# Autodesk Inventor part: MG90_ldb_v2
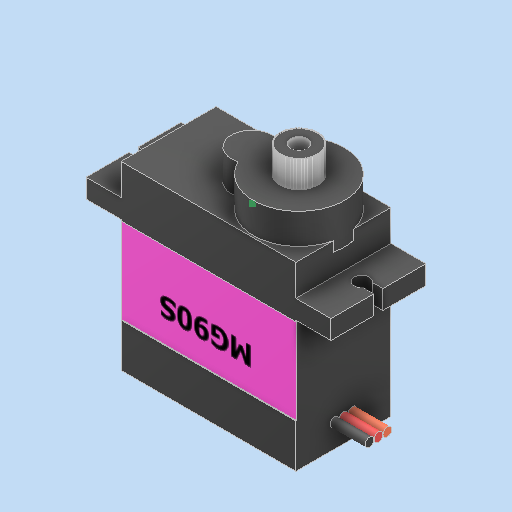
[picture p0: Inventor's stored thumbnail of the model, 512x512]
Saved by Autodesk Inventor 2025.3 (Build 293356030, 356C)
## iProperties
Created: 2019-07
Part Number: MG90_ldb_v2
Material: Steel
Document SubType Name: Modeling
Designer: Ryzen5700u
Density: 7.85 g/cm^3
Appearance: Default
Author: Ryzen5700u
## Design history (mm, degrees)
node "Geometria corretta1"
  node "Schizzo8-Invisible"
node "Solido1"
sketch "Schizzo2-Invisible"
sketch "Schizzo9-Invisible"
node "Schizzo11-Invisible"
node "Schizzo12-Invisible"
node "Schizzo6-Invisible"
sketch "Schizzo10-Invisible"
node "Schizzo7-Invisible"
node "Schizzo13-Invisible"
sketch "Schizzo1"
  geometry: L1 (23, -4.915)-(23, 0) reference; L2 (23, 0)-(0, 0) reference; L3 (0, 0)-(0, -12.5) reference; L4 (0, -12.5)-(23, -12.5) reference; L5 (23, -12.5)-(23, -7.585) reference; A1 r 6 centre (17.15, -6.25) between (23, -4.915) and (11.734, -3.666) reference; A2 r 6 centre (17.15, -6.25) between (11.734, -8.834) and (23, -7.585) reference; A3 r 2.7 centre (10.95, -6.25) between (11.734, -3.666) and (11.734, -8.834) reference; 1 further point
extrude "Estrusione1" join sketch "Schizzo1" distance "d0" = 1.3; taper "d1" = 0 deg
sketch "Schizzo2"
  geometry: L1 (4.6, 0)-(4.6, -12.5) reference; L2 (4.6, 0)-(0, 0) reference; L3 (0, 0)-(0, -5.65) reference; L4 (1.4, -5.65)-(0, -5.65) reference; L5 (1.4, -6.85)-(0, -6.85) reference; L6 (0, -6.85)-(0, -12.5) reference; L7 (4.6, -12.5)-(0, -12.5) reference; L8 (27.6, -12.5)-(27.6, 0) reference; L9 (27.6, -12.5)-(32.2, -12.5) reference; L10 (32.2, -12.5)-(32.2, -6.85) reference; L11 (30.8, -6.85)-(32.2, -6.85) reference; L12 (30.8, -5.65)-(32.2, -5.65) reference; L13 (32.2, -5.65)-(32.2, 0) reference; L14 (27.6, 0)-(32.2, 0) reference; A1 r 1 centre (2.2, -6.25) between (1.4, -6.85) and (1.4, -5.65) reference; A2 r 1 centre (30, -6.25) between (30.8, -5.65) and (30.8, -6.85) reference; 1 further point
extrude "Estrusione2" cut sketch "Schizzo2" distance "d5" = 1.8; taper "d6" = 0 deg
sketch "Schizzo3"
  geometry: L1 (4.6, 0)-(4.6, -12.5) reference; L2 (4.6, 0)-(0, 0) reference; L3 (0, 0)-(0, -5.65) reference; L4 (0, -5.65)-(1.4, -5.65) reference; L5 (1.4, -6.85)-(0, -6.85) reference; L6 (0, -6.85)-(0, -12.5) reference; L7 (4.6, -12.5)-(0, -12.5) reference; L8 (27.6, -12.5)-(27.6, 0) reference; L9 (27.6, -12.5)-(32.2, -12.5) reference; L10 (32.2, -12.5)-(32.2, -6.85) reference; L11 (32.2, -6.85)-(30.8, -6.85) reference; L12 (30.8, -5.65)-(32.2, -5.65) reference; L13 (32.2, -5.65)-(32.2, 0) reference; L14 (27.6, 0)-(32.2, 0) reference; A1 r 1 centre (2.2, -6.25) between (1.4, -6.85) and (1.4, -5.65) reference; A2 r 1 centre (30, -6.25) between (30.8, -5.65) and (30.8, -6.85) reference; 1 further point
extrude "Estrusione3" join sketch "Schizzo3" distance "d7" = 1.5; taper "d8" = 0 deg
sketch "Schizzo4"
  geometry: L1 (-0.548, -2.337)-(-0.45, -2.358) reference; L2 (-0.569, -2.434)-(-0.548, -2.337) reference; L3 (-0.694, -2.298)-(-0.725, -2.393) reference; L4 (-0.789, -2.267)-(-0.694, -2.298) reference; L5 (-0.82, -2.362)-(-0.789, -2.267) reference; L6 (-0.93, -2.213)-(-0.971, -2.304) reference; L7 (-1.022, -2.172)-(-0.93, -2.213) reference; L8 (-1.062, -2.263)-(-1.022, -2.172) reference; L9 (-1.157, -2.103)-(-1.206, -2.19) reference; L10 (-1.243, -2.053)-(-1.157, -2.103) reference; L11 (-1.293, -2.14)-(-1.243, -2.053) reference; L12 (-1.37, -1.971)-(-1.429, -2.052) reference; L13 (-1.451, -1.912)-(-1.37, -1.971) reference; L14 (-1.51, -1.993)-(-1.451, -1.912) reference; L15 (-1.569, -1.817)-(-1.635, -1.891) reference; L16 (-1.643, -1.75)-(-1.569, -1.817) reference; L17 (-1.71, -1.824)-(-1.643, -1.75) reference; L18 (-1.75, -1.643)-(-1.824, -1.71) reference; L19 (-1.817, -1.569)-(-1.75, -1.643) reference; L20 (-1.891, -1.635)-(-1.817, -1.569) reference; L21 (-1.912, -1.451)-(-1.993, -1.51) reference; L22 (-1.971, -1.37)-(-1.912, -1.451) reference; L23 (-2.052, -1.429)-(-1.971, -1.37) reference; L24 (-2.053, -1.243)-(-2.14, -1.293) reference; L25 (-2.103, -1.157)-(-2.053, -1.243) reference; L26 (-2.19, -1.206)-(-2.103, -1.157) reference; L27 (-2.172, -1.022)-(-2.263, -1.062) reference; L28 (-2.213, -0.93)-(-2.172, -1.022) reference; L29 (-2.304, -0.971)-(-2.213, -0.93) reference; L30 (-2.267, -0.789)-(-2.362, -0.82) reference; L31 (-2.298, -0.694)-(-2.267, -0.789) reference; L32 (-2.393, -0.725)-(-2.298, -0.694) reference; L33 (-2.337, -0.548)-(-2.434, -0.569) reference; L34 (-2.358, -0.45)-(-2.337, -0.548) reference; L35 (-2.455, -0.471)-(-2.358, -0.45) reference; L36 (-2.382, -0.301)-(-2.481, -0.311) reference; L37 (-2.392, -0.201)-(-2.382, -0.301) reference; L38 (-2.491, -0.212)-(-2.392, -0.201) reference; L39 (-2.4, -0.05)-(-2.499, -0.05) reference; L40 (-2.4, 0.05)-(-2.4, -0.05) reference; L41 (-2.499, 0.05)-(-2.4, 0.05) reference; L42 (-2.392, 0.201)-(-2.491, 0.212) reference; L43 (-2.382, 0.301)-(-2.392, 0.201) reference; L44 (-2.481, 0.311)-(-2.382, 0.301) reference; L45 (-2.358, 0.45)-(-2.455, 0.471) reference; L46 (-2.337, 0.548)-(-2.358, 0.45) reference; L47 (-2.434, 0.569)-(-2.337, 0.548) reference; L48 (-2.298, 0.694)-(-2.393, 0.725) reference; L49 (-2.267, 0.789)-(-2.298, 0.694) reference; L50 (-2.362, 0.82)-(-2.267, 0.789) reference; L51 (-2.213, 0.93)-(-2.304, 0.971) reference; L52 (-2.172, 1.022)-(-2.213, 0.93) reference; L53 (-2.263, 1.062)-(-2.172, 1.022) reference; L54 (-2.103, 1.157)-(-2.19, 1.206) reference; L55 (-2.053, 1.243)-(-2.103, 1.157) reference; L56 (-2.14, 1.293)-(-2.053, 1.243) reference; L57 (-1.971, 1.37)-(-2.052, 1.429) reference; L58 (-1.912, 1.451)-(-1.971, 1.37) reference; L59 (-1.993, 1.51)-(-1.912, 1.451) reference; L60 (-1.817, 1.569)-(-1.891, 1.635) reference; L61 (-1.75, 1.643)-(-1.817, 1.569) reference; L62 (-1.824, 1.71)-(-1.75, 1.643) reference; L63 (-1.643, 1.75)-(-1.71, 1.824) reference; L64 (-1.569, 1.817)-(-1.643, 1.75) reference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; A1 r 6 centre (0, 0) between (-5.416, -2.584) and (-5.416, 2.584) reference; A2 r 2.7 centre (-6.2, 0) between (-5.416, 2.584) and (-5.416, -2.584) reference; A3 r 2.5 centre (0, 0) between (-0.725, -2.393) and (-0.569, -2.434) reference; A4 r 2.5 centre (0, 0) between (-0.971, -2.304) and (-0.82, -2.362) reference; A5 r 2.5 centre (0, 0) between (-1.206, -2.19) and (-1.062, -2.263) reference; A6 r 2.5 centre (0, 0) between (-1.429, -2.052) and (-1.293, -2.14) reference; A7 r 2.5 centre (0, 0) between (-1.635, -1.891) and (-1.51, -1.993) reference; A8 r 2.5 centre (0, 0) between (-1.824, -1.71) and (-1.71, -1.824) reference; A9 r 2.5 centre (0, 0) between (-1.993, -1.51) and (-1.891, -1.635) reference; A10 r 2.5 centre (0, 0) between (-2.14, -1.293) and (-2.052, -1.429) reference; A11 r 2.5 centre (0, 0) between (-2.263, -1.062) and (-2.19, -1.206) reference; A12 r 2.5 centre (0, 0) between (-2.362, -0.82) and (-2.304, -0.971) reference; A13 r 2.5 centre (0, 0) between (-2.434, -0.569) and (-2.393, -0.725) reference; A14 r 2.5 centre (0, 0) between (-2.481, -0.311) and (-2.455, -0.471) reference; A15 r 2.5 centre (0, 0) between (-2.499, -0.05) and (-2.491, -0.212) reference; A16 r 2.5 centre (0, 0) between (-2.491, 0.212) and (-2.499, 0.05) reference; A17 r 2.5 centre (0, 0) between (-2.455, 0.471) and (-2.481, 0.311) reference; A18 r 2.5 centre (0, 0) between (-2.393, 0.725) and (-2.434, 0.569) reference; A19 r 2.5 centre (0, 0) between (-2.304, 0.971) and (-2.362, 0.82) reference; A20 r 2.5 centre (0, 0) between (-2.19, 1.206) and (-2.263, 1.062) reference; A21 r 2.5 centre (0, 0) between (-2.052, 1.429) and (-2.14, 1.293) reference; A22 r 2.5 centre (0, 0) between (-1.891, 1.635) and (-1.993, 1.51) reference; A23 r 2.5 centre (0, 0) between (-1.71, 1.824) and (-1.824, 1.71) reference; A24 r 2.5 centre (0, 0) between (-1.51, 1.993) and (-1.635, 1.891) reference; A25 r 2.5 centre (0, 0) between (-1.293, 2.14) and (-1.429, 2.052) reference; A26 r 2.5 centre (0, 0) between (-1.062, 2.263) and (-1.206, 2.19) reference; A27 r 2.5 centre (0, 0) between (-0.82, 2.362) and (-0.971, 2.304) reference; A28 r 2.5 centre (0, 0) between (-0.569, 2.434) and (-0.725, 2.393) reference; A29 r 2.5 centre (0, 0) between (-0.311, 2.481) and (-0.471, 2.455) reference; A30 r 2.5 centre (0, 0) between (-0.05, 2.499) and (-0.212, 2.491) reference; A31 r 2.5 centre (0, 0) between (0.212, 2.491) and (0.05, 2.499) reference; A32 r 2.5 centre (0, 0) between (0.471, 2.455) and (0.311, 2.481) reference; A33 r 2.5 centre (0, 0) between (0.725, 2.393) and (0.569, 2.434) reference; A34 r 2.5 centre (0, 0) between (0.971, 2.304) and (0.82, 2.362) reference; A35 r 2.5 centre (0, 0) between (1.206, 2.19) and (1.062, 2.263) reference; A36 r 2.5 centre (0, 0) between (1.429, 2.052) and (1.293, 2.14) reference; A37 r 2.5 centre (0, 0) between (1.635, 1.891) and (1.51, 1.993) reference; A38 r 2.5 centre (0, 0) between (1.824, 1.71) and (1.71, 1.824) reference; A39 r 2.5 centre (0, 0) between (1.993, 1.51) and (1.891, 1.635) reference; A40 r 2.5 centre (0, 0) between (2.14, 1.293) and (2.052, 1.429) reference; A41 r 2.5 centre (0, 0) between (2.263, 1.062) and (2.19, 1.206) reference; A42 r 2.5 centre (0, 0) between (2.362, 0.82) and (2.304, 0.971) reference; A43 r 2.5 centre (0, 0) between (2.434, 0.569) and (2.393, 0.725) reference; A44 r 2.5 centre (0, 0) between (2.481, 0.311) and (2.455, 0.471) reference; A45 r 2.5 centre (0, 0) between (2.499, 0.05) and (2.491, 0.212) reference; A46 r 2.5 centre (0, 0) between (2.491, -0.212) and (2.499, -0.05) reference; A47 r 2.5 centre (0, 0) between (2.455, -0.471) and (2.481, -0.311) reference; A48 r 2.5 centre (0, 0) between (2.393, -0.725) and (2.434, -0.569) reference; A49 r 2.5 centre (0, 0) between (2.304, -0.971) and (2.362, -0.82) reference; A50 r 2.5 centre (0, 0) between (2.19, -1.206) and (2.263, -1.062) reference; A51 r 2.5 centre (0, 0) between (2.052, -1.429) and (2.14, -1.293) reference; A52 r 2.5 centre (0, 0) between (1.891, -1.635) and (1.993, -1.51) reference; A53 r 2.5 centre (0, 0) between (1.71, -1.824) and (1.824, -1.71) reference; A54 r 2.5 centre (0, 0) between (1.51, -1.993) and (1.635, -1.891) reference; A55 r 2.5 centre (0, 0) between (1.293, -2.14) and (1.429, -2.052) reference; A56 r 2.5 centre (0, 0) between (1.062, -2.263) and (1.206, -2.19) reference; A57 r 2.5 centre (0, 0) between (0.82, -2.362) and (0.971, -2.304) reference; A58 r 2.5 centre (0, 0) between (0.569, -2.434) and (0.725, -2.393) reference; A59 r 2.5 centre (0, 0) between (0.311, -2.481) and (0.471, -2.455) reference; A60 r 2.5 centre (0, 0) between (0.05, -2.499) and (0.212, -2.491) reference; A61 r 2.5 centre (0, 0) between (-0.212, -2.491) and (-0.05, -2.499) reference; A62 r 2.5 centre (0, 0) between (-0.471, -2.455) and (-0.311, -2.481) reference; 1 further point
extrude "Estrusione4" cut sketch "Schizzo4" distance "d9" = 0.7; taper "d10" = 0 deg
sketch "Schizzo5"
  geometry: C1 r 1.1 at (0, 0) reference; C2 r 3.334 at (0, 0); 1 further point
  constraints: 1 centre point, 1 coincident
extrude "Estrusione5" cut sketch "Schizzo5" distance "d11" = 1.2; taper "d12" = 0 deg
node "Modifica diretta1"
node "Modifica diretta2"
sketch "Schizzo6"
  geometry: L1 (23, 0)-(23, 17.2) reference; L2 (0, 17.2)-(0, 0) reference; L3 (23, 5.728)-(0, 5.728); L4 (0, 5.728)-(0, 17.02); L5 (0, 17.02)-(23, 17.02); L6 (23, 17.02)-(23, 5.728); 3 further points
  constraints: 8 end point, 2 parallel, 2 point on line, 1 horizontal, 1 perpendicular
extrude "Estrusione6" cut sketch "Schizzo6" distance "d19" = 0.1; taper "d20" = 0 deg
sketch "Schizzo7"
  geometry: L1 (17.189, 8.713)-(9.814, 8.713); L2 (9.814, 8.713)-(9.814, 5.068); L3 (9.814, 5.068)-(17.189, 5.068); L4 (17.189, 5.068)-(17.189, 8.713); 1 further point
  constraints: 2 other
node "Solido2"
node "Linea chiusa proiettata1"
node "Linea chiusa proiettata2"
node "Linea chiusa proiettata3"
node "Linea chiusa proiettata4"
node "Linea chiusa proiettata5"
node "Linea chiusa proiettata6"
feature "Sposta1" dims "d13" = -1.5
feature "Sposta2" dims "d16" = -1.5
other parameters: "d14" = 0, "d15" = 0, "d17" = 0, "d18" = 0
